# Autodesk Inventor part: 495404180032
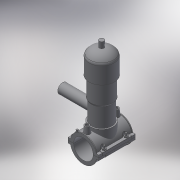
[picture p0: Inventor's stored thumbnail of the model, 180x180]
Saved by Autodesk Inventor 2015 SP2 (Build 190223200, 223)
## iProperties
Created: 2017-07
Part Number: 495404180032
Material: Generic
Description: PLASSON TAPPING VALVE 180-32
Document SubType Name: Modeling
Designer: KIM
Density: 1 g/cm^3
Appearance: Default
Author: KIM
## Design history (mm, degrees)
derived "495404-4954S4.ipt"
feature "Solid1::495404-4954S4.ipt"
feature "Solid2::495404-4954S4.ipt"
tag "TaggingFeature1"
body "Solid1"
body "Solid2"
other parameters: "d3" = 45, "d4" = 118, "d5" = 0, "d6" = 0.1, "d8" = 0, "d19" = 6, "d20" = 6, "d21" = 70.8, "d23" = 0, "d24" = 35.4, "d26" = 0, "d27" = 3, "d28" = 3, "d29" = 3, "d31" = 6, "d32" = 0, "d33" = 0, "d34" = 0.6, "d40" = 109.512, "d47" = 151.3, "d70" = 15, "d72" = 0, "d73" = 6, "d75" = 5, "d76" = 0, "d77" = 9, "d79" = 15, "d80" = 47.2, "d82" = 5 deg, "d84" = 4, "d85" = 14, "d86" = 0, "d87" = 3, "d88" = 0, "d89" = 1, "d90" = 1, "d91" = 94.4, "d92" = 0, "d93" = 0.5, "d94" = 94.73684, "d96" = 216.918, "d97" = 2.36, "d98" = 0, "d120" = 140 deg, "d121" = 24.228, "d122" = 20 deg, "d123" = 421.2, "d124" = 126.36, "d126" = 0, "d143" = 185.4, "d145" = 23.53846, "d149" = 2.7, "d150" = 25.89231, "d153" = 118, "d154" = 0, "d156" = 105.3, "d157" = 160 deg, "d159" = 6.12, "d161" = 2.7, "d162" = 70.8, "d163" = 0, "d167" = 18, "d168" = 102.73171, "d170" = 3, "d172" = 0, "d173" = 1, "d176" = 20 deg, "d177" = 12.6, "d178" = 30.6, "d180" = 0, "d183" = 12.24, "d184" = 10.08, "d185" = 38.35, "d186" = 38.35, "d187" = 105.3, "d188" = 9.18, "d189" = 12.6, "d190" = 0, "d191" = 157.95, "d193" = 6.8, "d194" = 2.95, "d195" = 90 deg, "d197" = 0, "d199" = 0, "d205" = 14.64, "d206" = 81.33333, "d207" = 244, "d208" = 224.48, "d209" = 207.4, "d210" = 200.08, "d211" = 146.4, "d212" = 85.4, "d213" = 65.88, "d214" = 73.2, "d216" = 19.52, "d217" = 70.76, "d218" = 80.52, "d222" = 0, "d223" = 210.6, "d224" = 126, "d225" = 46, "d226" = 32, "d229" = 126, "d230" = 0, "H_" = 126, "L_" = 118, "d_t" = 6, "d_1" = 32, "H_1" = 46, "H_2" = 244, "d148" = 2.7, "d160" = 2.7, "d169" = 3, "d192" = 6.8, "d228" = 25.6
